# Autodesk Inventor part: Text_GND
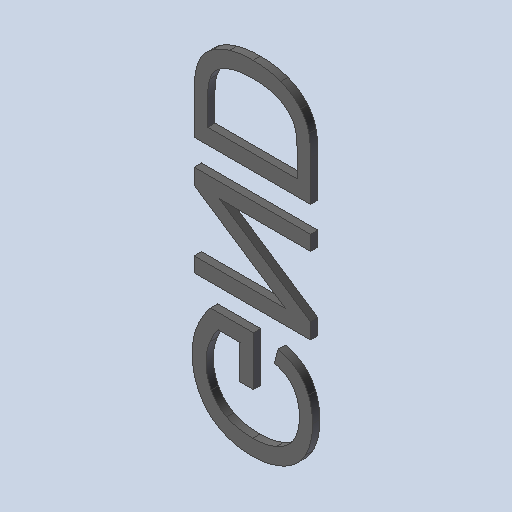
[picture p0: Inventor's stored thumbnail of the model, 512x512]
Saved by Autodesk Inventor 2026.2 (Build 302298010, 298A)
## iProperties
Created: 2026-10
Part Number: Text_GND
Material: Générique
Document SubType Name: Modeling
Designer: mel
Density: 1 g/cm^3
Appearance: Par défaut
Author: mel
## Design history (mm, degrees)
feature "Base1"
feature "Base2"
feature "Base3"
node "Solide1"
node "Solide2"
node "Solide3"
